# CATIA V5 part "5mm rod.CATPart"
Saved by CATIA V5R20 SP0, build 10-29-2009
Part number: 5mm rod
Source: Unknown
Bounding box of the stored display mesh (mm): x -2.5 to 2.5, y 0 to 21.5, z -2.482 to 2.482
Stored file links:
  C:\Users\Ikarus\OneDrive - FH JOANNEUM\BAC - Arbeit 1\CAD Modell\CAD-Modell-Step files\Platzhalter\5mm rod.CATPart
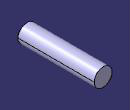
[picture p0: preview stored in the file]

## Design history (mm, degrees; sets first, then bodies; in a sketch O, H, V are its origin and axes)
Body1 (main body)
  Solid1 "Hauptkörper": solid without history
